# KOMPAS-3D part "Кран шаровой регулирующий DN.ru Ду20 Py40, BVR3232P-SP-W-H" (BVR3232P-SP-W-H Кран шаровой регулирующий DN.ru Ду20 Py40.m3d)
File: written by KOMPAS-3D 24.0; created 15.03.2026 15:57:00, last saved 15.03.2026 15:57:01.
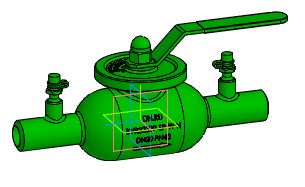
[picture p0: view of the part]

Document properties: Автор: Максим; Полное имя файла: D:\Rabota ebanaya\BVR3232P-SP-W-H Кран шаровой регулирующий Ду15-150\Типоразмеры\DN20\BVR3232P-SP-W-H Кран шаровой регулирующий DN.ru Ду20 Py40.m3d

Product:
- Body: Тело 1  | qty 1
    Масса: 3.176026
- Part/product: Кран шаровой регулирующий DN.ru Ду20 Py40  | designation BVR3232P-SP-W-H
    Масса: 1.7
    Раздел спецификации: Прочие изделия
    Примечание: D160-69407

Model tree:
1. Операция без истории:1

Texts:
  BVR3232P-SP-W-H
